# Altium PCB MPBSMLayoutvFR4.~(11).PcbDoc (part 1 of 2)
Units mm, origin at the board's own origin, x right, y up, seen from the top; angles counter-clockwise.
Board outline 131.7 x 110.39 mm, 4 copper layers (Top Layer, Power, GroundPlane, Bottom Layer), stack 2.286 mm thick; 156 components, 77 nets, 429 pads, 117 vias.
Unrouted connection lines stored in the file: 25.
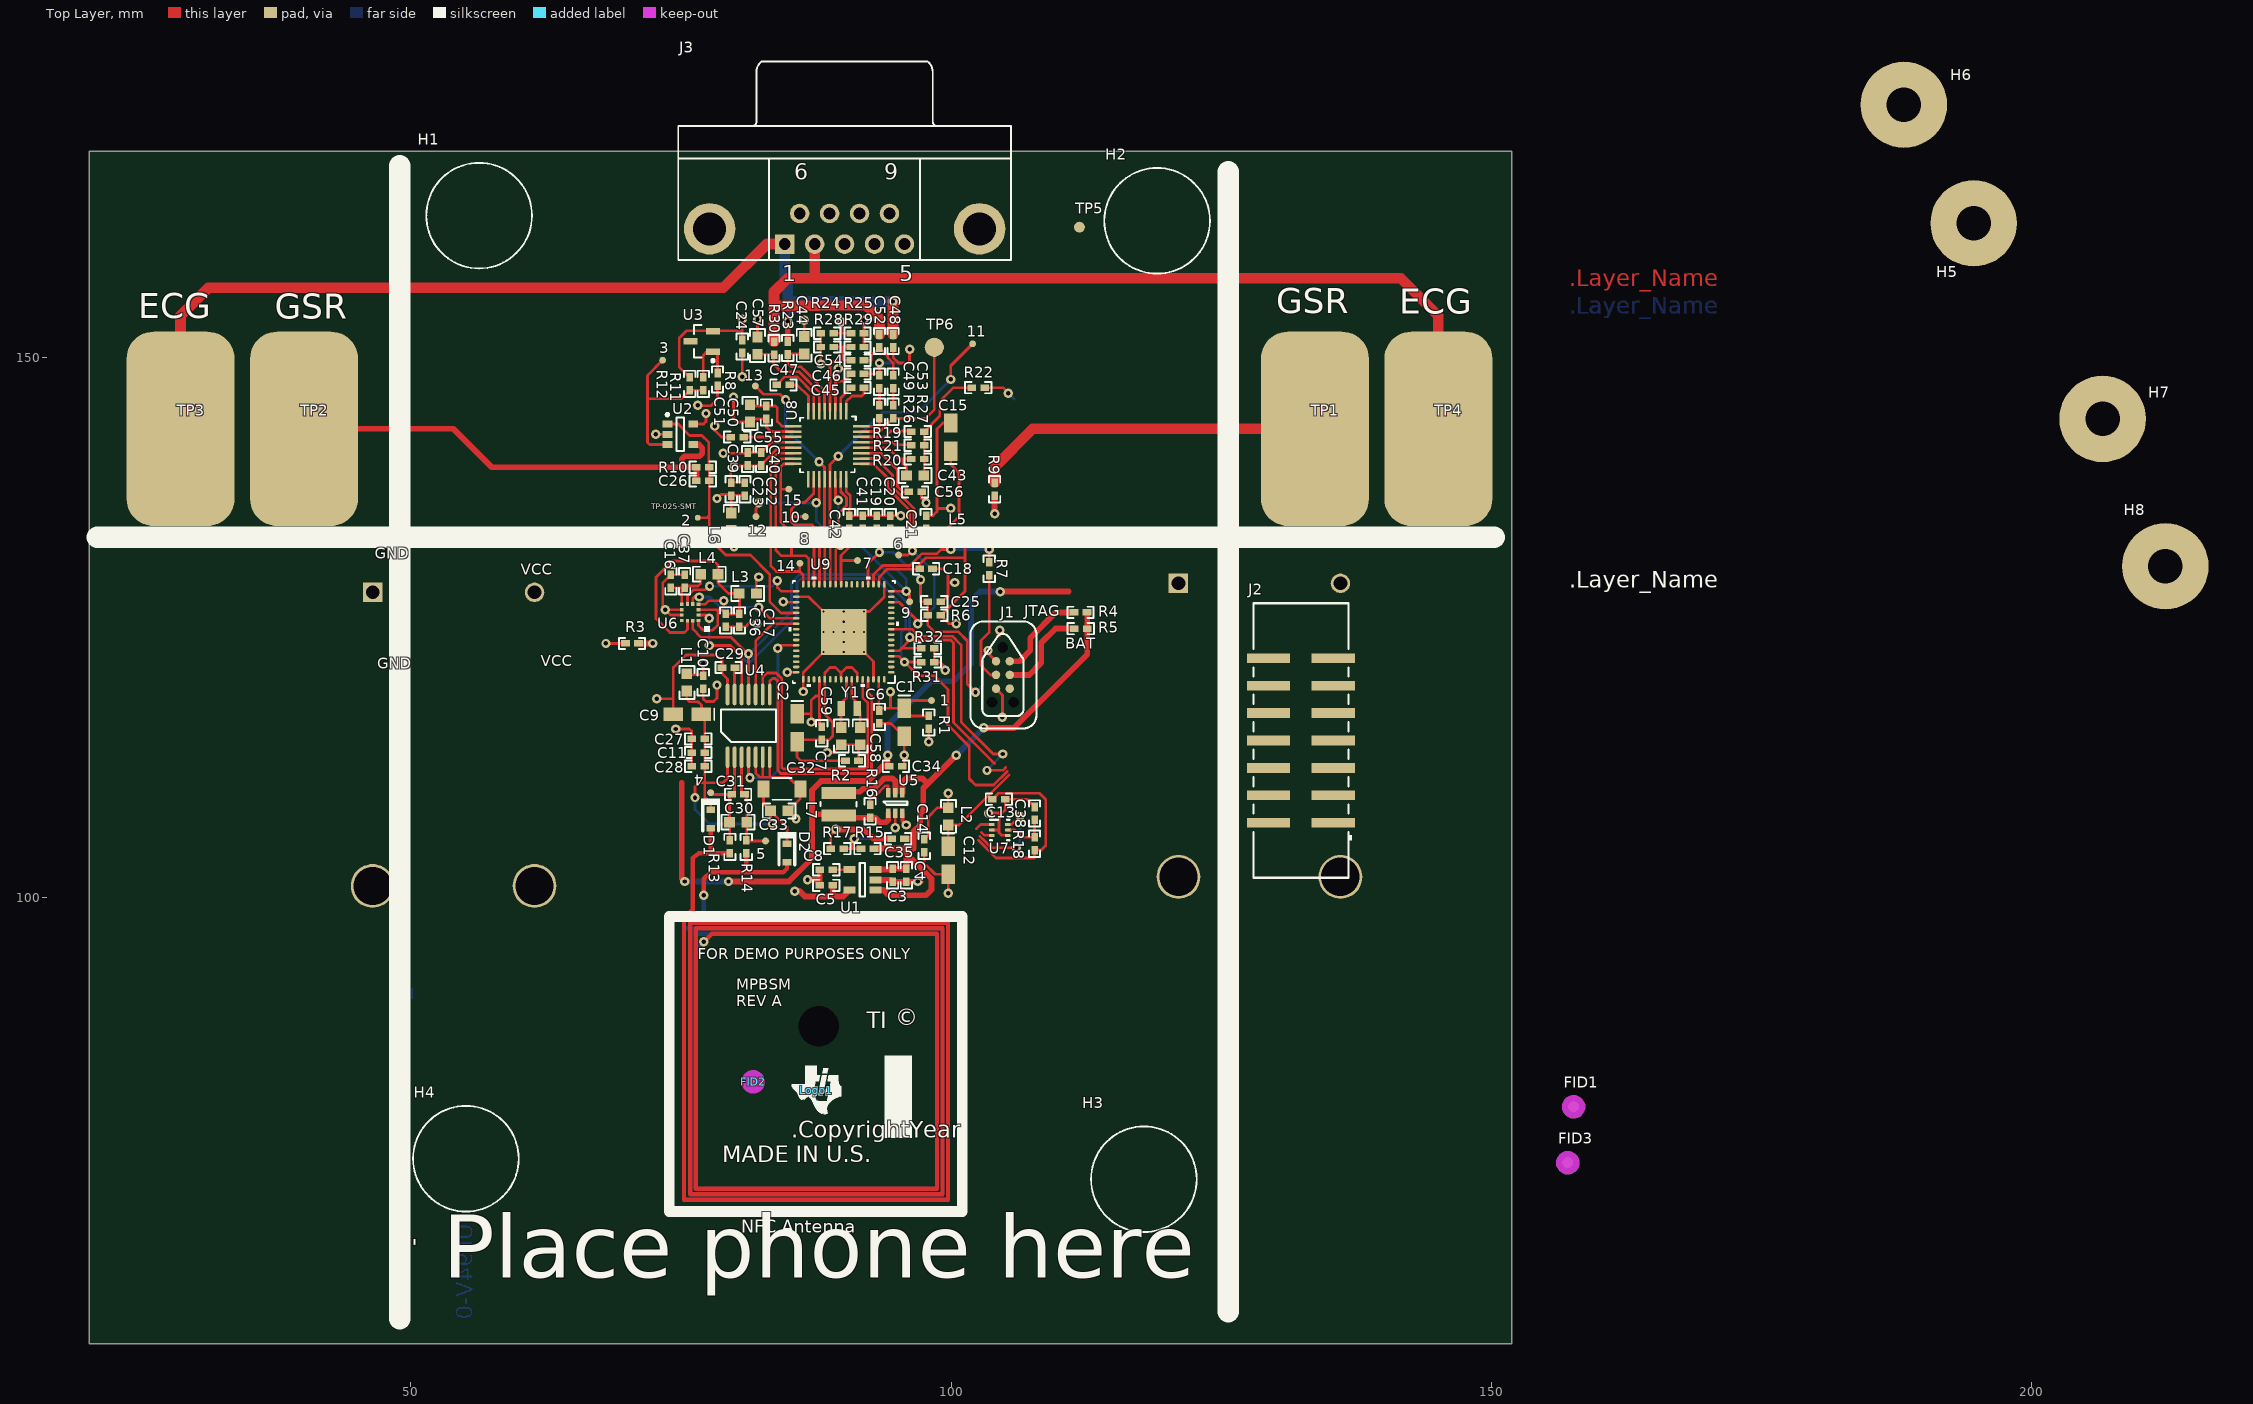
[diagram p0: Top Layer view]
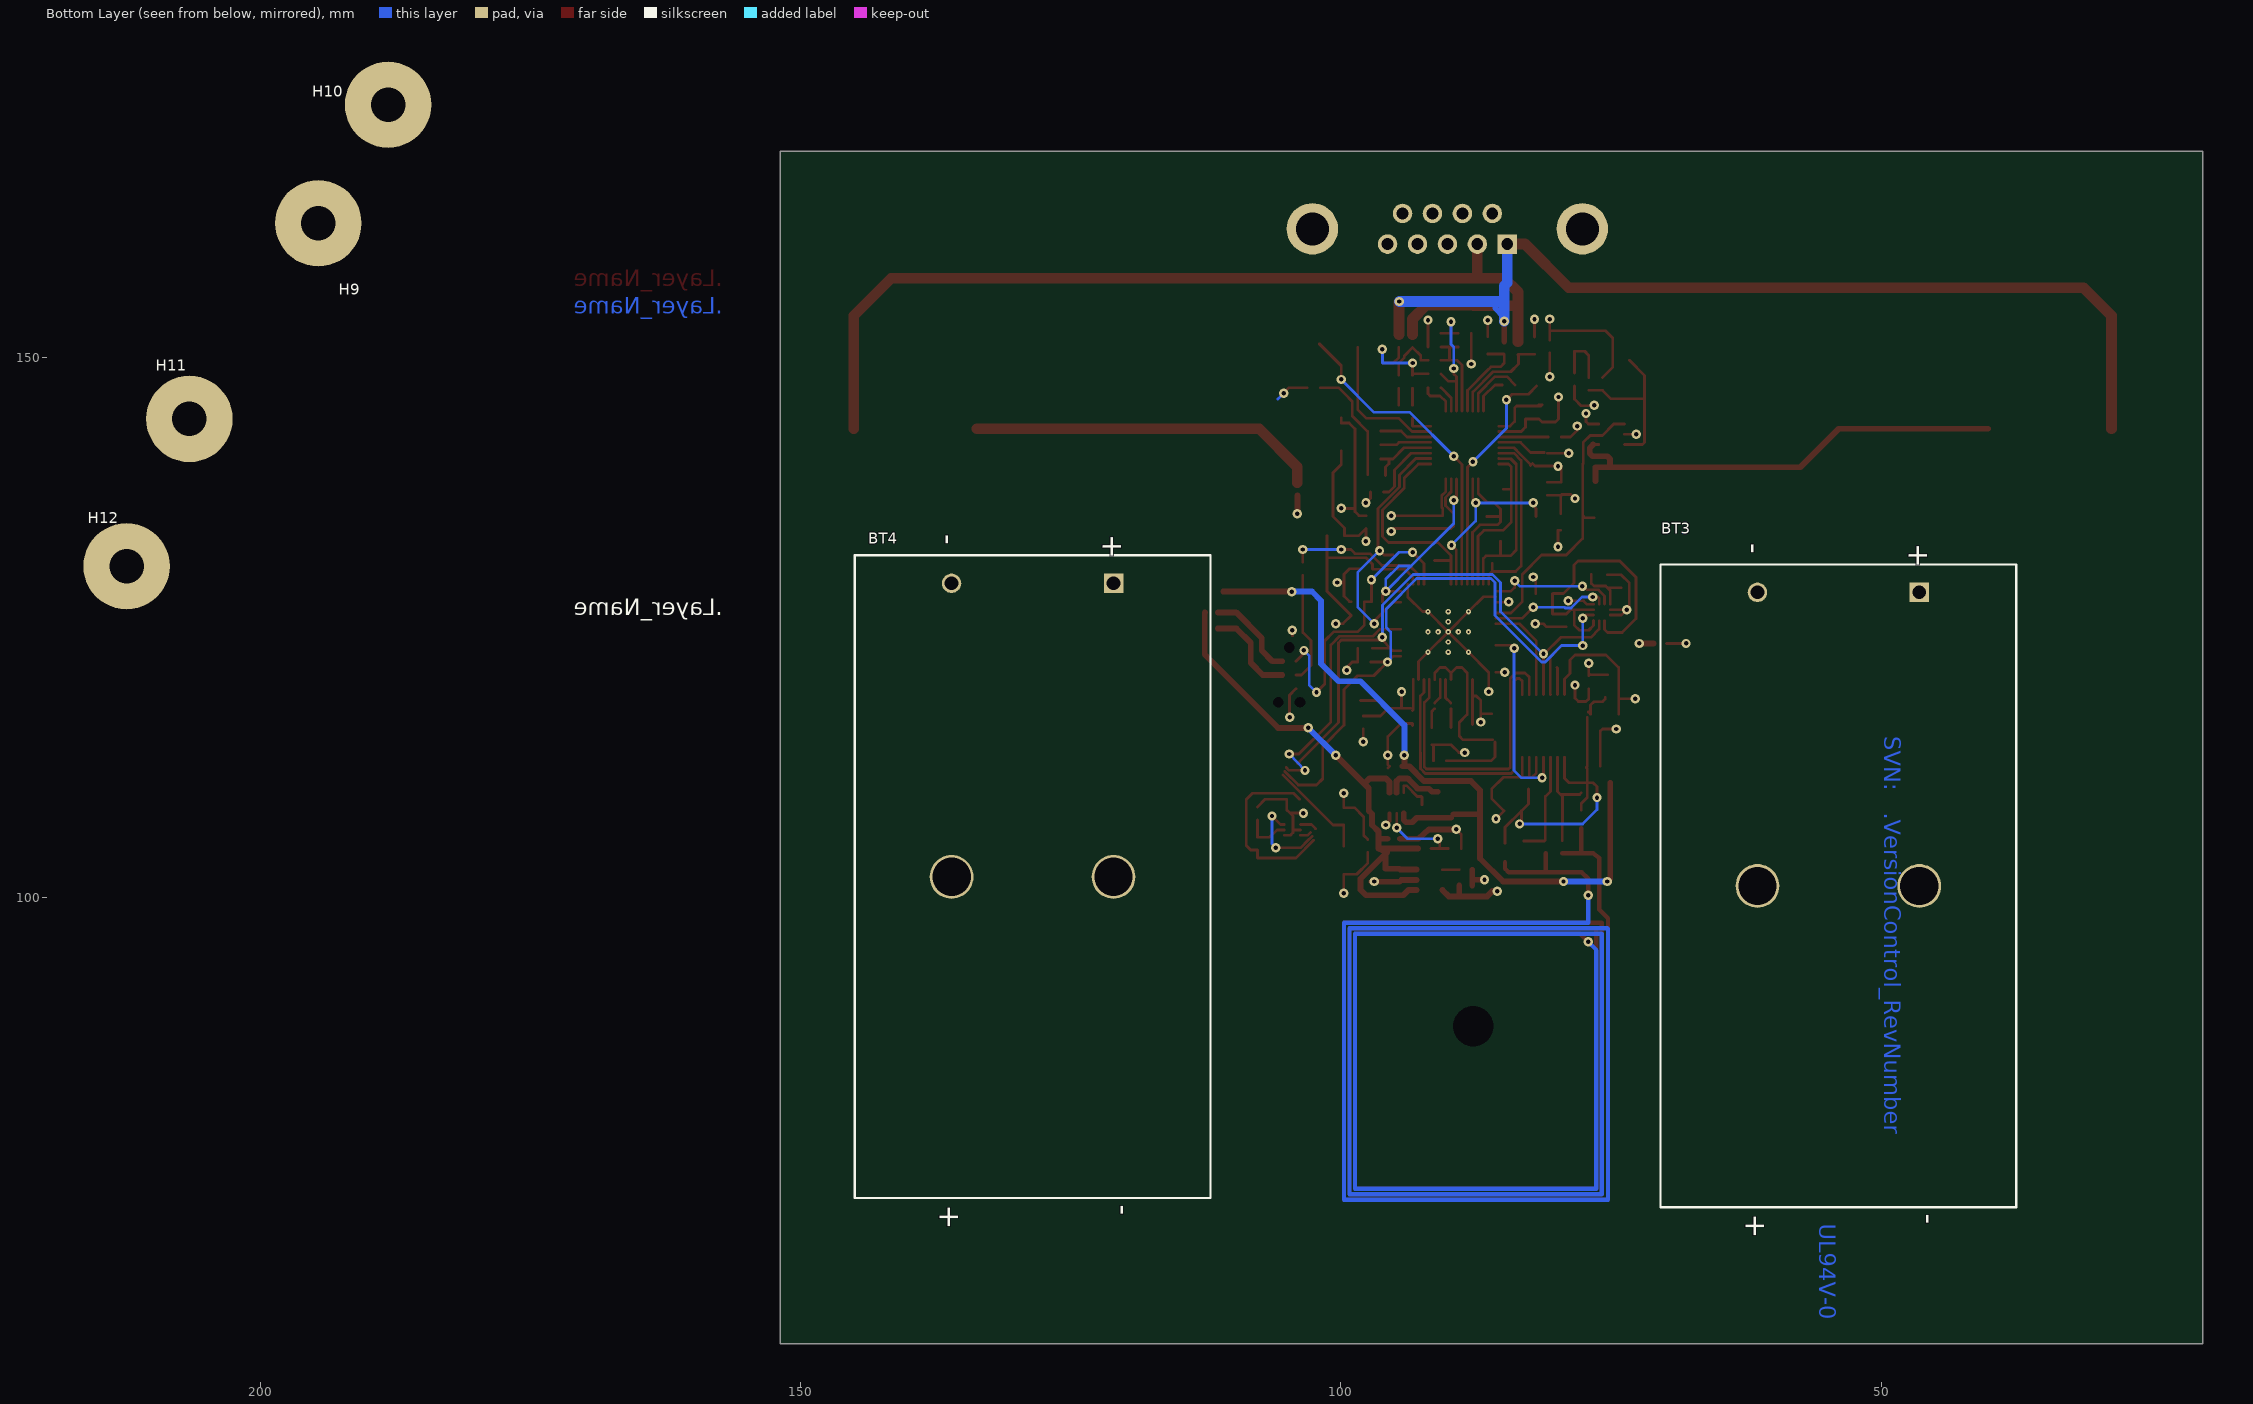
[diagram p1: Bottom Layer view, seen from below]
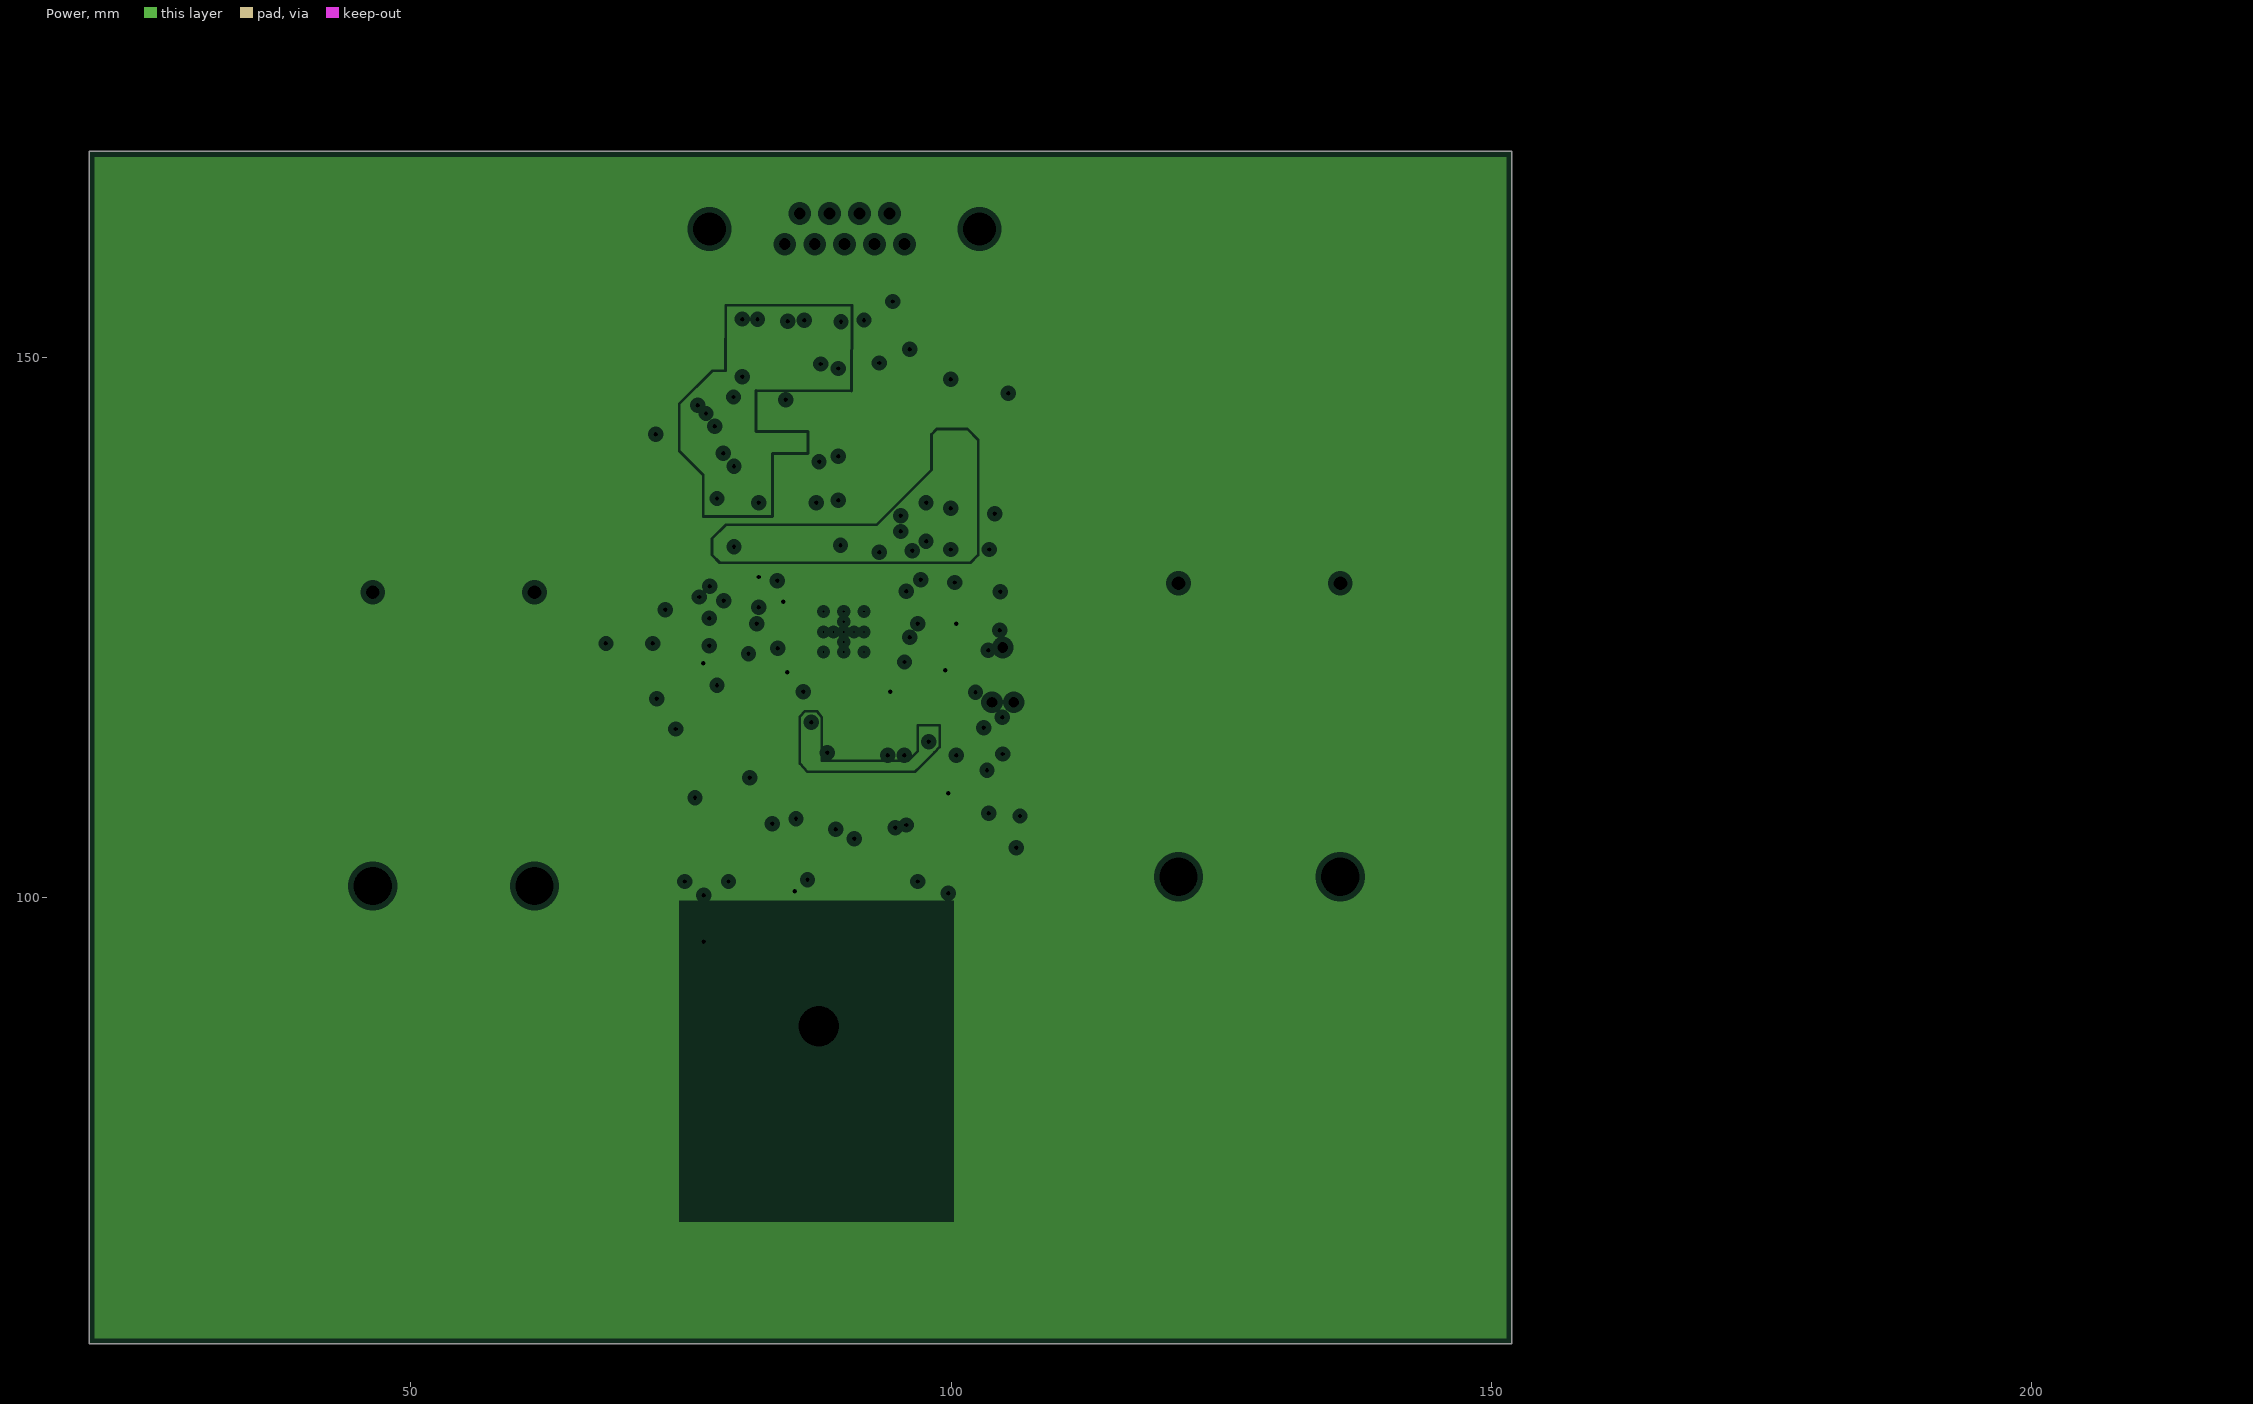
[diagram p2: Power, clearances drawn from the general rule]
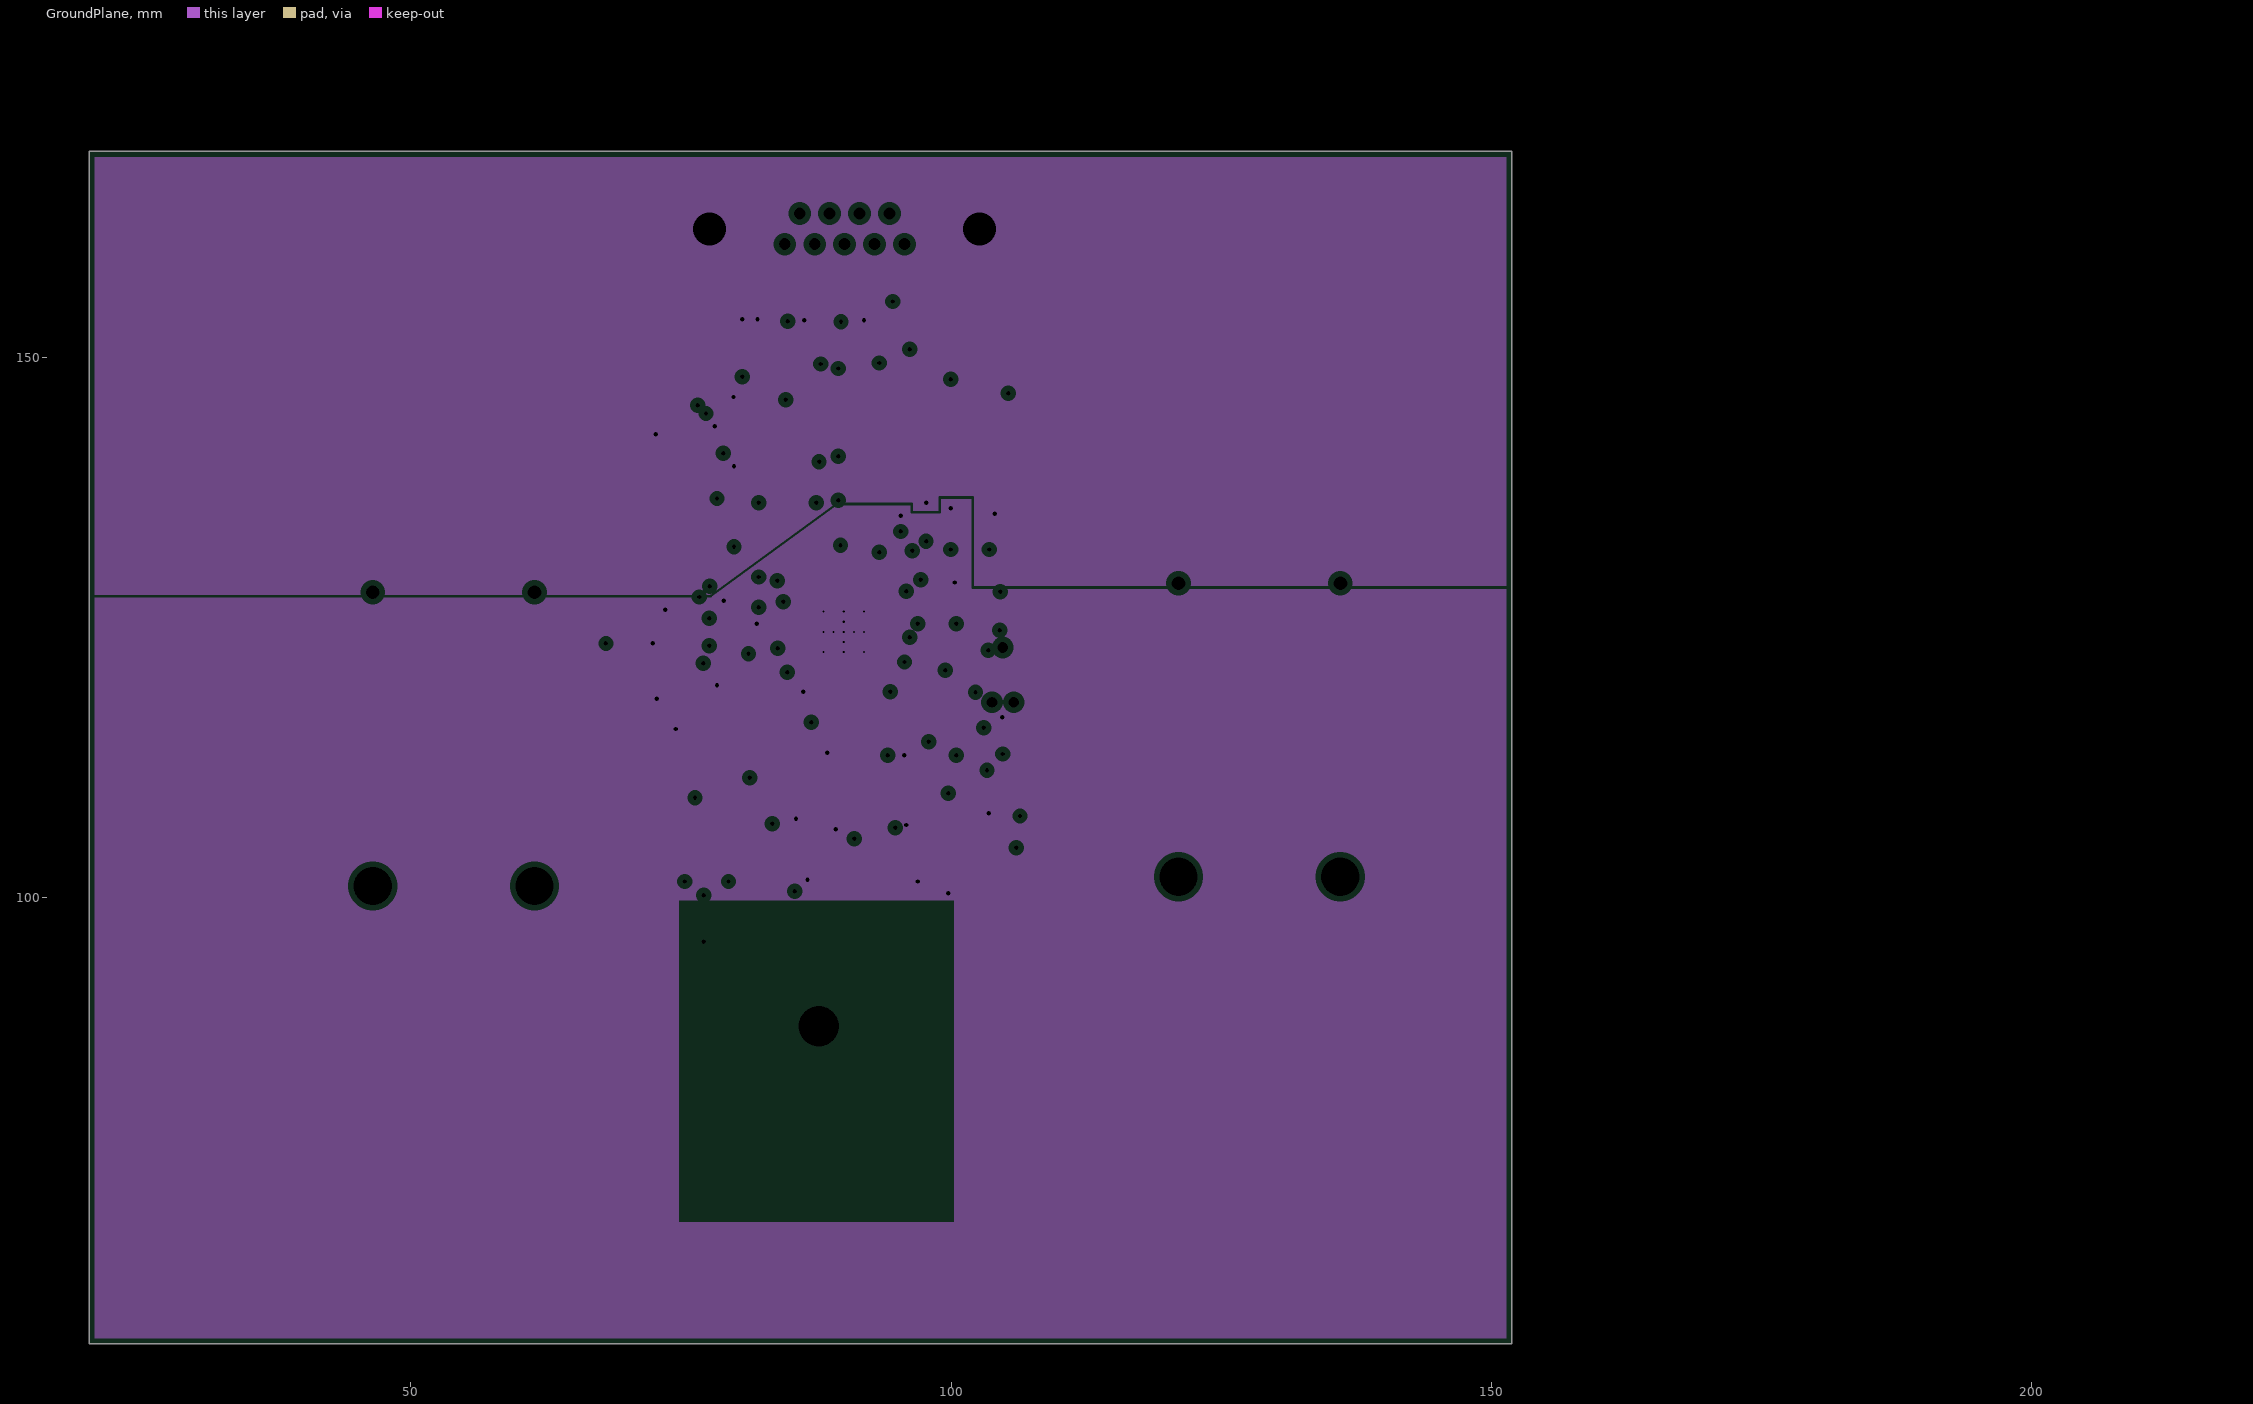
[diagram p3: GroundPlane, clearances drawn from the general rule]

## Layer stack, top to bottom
Top Solder: solder mask 0.0102, Solder Resist, Dk 3.5
Top Layer: signal copper 0.0356
Dielectric1: core 1.5037, FR-4, Dk 4.8
Power: plane copper 0.0356, net DVCC
Dielectric2: prepreg 0.32, FR-4, Dk 4.8
GroundPlane: plane copper 0.0356, net GND
Dielectric3: core 0.32, FR-4, Dk 4.8
Bottom Layer: signal copper 0.0356
Bottom Solder: solder mask 0.0102, Solder Resist, Dk 3.5

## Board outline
20.218,169.037 20.218,58.649 150.825,58.649 151.917,58.649 151.917,158.471 151.917,169.037 20.218,169.037

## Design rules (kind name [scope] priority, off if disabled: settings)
AcuteAngle [All] p1: minimum=4.50000000000000E+0001 checktracksonly=FALSE
AssemblyTestPointUsage [All] p1: valid=2
Clearance Clearance_BoardEdge_MountingHoles [OnCopper and InComponentClass('Mounting Holes') vs IsKeepOut] p1: gap=1.016
Clearance Clearance_BoardEdge_Poly [OnCopper and InPoly vs IsKeepOut] p2: gap=0.635
Clearance Clearance_BoardEdge [OnCopper and Not InComponentClass('Logo') and not InComponentClass('FiducialMark') and not InRegion(1000,500,4000,800) and Not IsKeepout vs IsKeepOut] p3: gap=1.905
Clearance Clearance_Poly [InPolygon] p4: gap=0.635
Clearance [All] p5: gap=0.1
ComponentClearance ComponentClearance_Shunt [InComponentClass('Header') vs InComponentClass('Shunt')] p1: gap=0 collisioncheckmode=3 verticalgap=0 showdistances=FALSE
ComponentClearance ComponentClearance_MountingHoles_FiducialMarks [InComponentClass('Mounting Holes') vs InComponentClass('FiducialMark')] p2: gap=1.27 collisioncheckmode=3 verticalgap=0.254 showdistances=FALSE
ComponentClearance ComponentClearance_Logo [InComponentClass('Logo')] p3: gap=1.27 collisioncheckmode=3 verticalgap=0.254 showdistances=FALSE
ComponentClearance ComponentClearance_ScrewToNut [(HasFootprint('NY PMS 440 0025 PH')) vs (HasFootprint('Keystone_1902C'))] p4: gap=0.127 collisioncheckmode=3 verticalgap=0.254 showdistances=FALSE
ComponentClearance ComponentClearance_MountingHoles [InComponentClass('Mounting Holes')] p5: gap=6.35 collisioncheckmode=3 verticalgap=2540 showdistances=FALSE
ComponentClearance ComponentClearance_SmallPassives [HasFootprint('0201*') or HasFootprint('0402*') or HasFootprint('0508') or HasFootprint('0603*') or HasFootprint('0612') or HasFootprint('0805*') or HasFootprint('0815*') or HasFootprint('0830*') or HasFootprint('1206*') or HasFootprint('1210*') or HasFootprint('1808*') or HasFootprint('1812*') or HasFootprint('1825*') or HasFootprint('2010*') or HasFootprint('2220*') or HasFootprint('2225*') or HasFootprint('2512*') or HasFootprint('2728*') or HasFootprint('3518*') vs HasFootprint('0201*') or HasFootprint('0402*') or HasFootprint('0508') or HasFootprint('0603*') or HasFootprint('0612') or HasFootprint('0805*') or HasFootprint('0815*') or HasFootprint('0830*') or HasFootprint('1206*') or HasFootprint('1210*') or HasFootprint('1808*') or HasFootprint('1812*') or HasFootprint('1825*') or HasFootprint('2010*') or HasFootprint('2220*') or HasFootprint('2225*') or HasFootprint('2512*') or HasFootprint('2728*') or HasFootprint('3518*')] p6: gap=0.508 collisioncheckmode=3 verticalgap=0.254 showdistances=FALSE
ComponentClearance ComponentClearance_THtoSMT [IsThruComponent vs IsSMTComponent] p7: gap=2.54 collisioncheckmode=3 verticalgap=0.762 showdistances=FALSE
ComponentClearance ComponentClearance_THtoTH [IsThruComponent vs IsThruComponent] p8: gap=3 collisioncheckmode=3 verticalgap=0.762 showdistances=FALSE
ComponentClearance [All] p9: gap=1.016 collisioncheckmode=3 verticalgap=0.254 showdistances=FALSE
DiffPairsRouting [All] p1: maxlimit=2.54 minlimit=0.254 mostfreqgap=0.254 toplayer_minwidth=0.381 toplayer_maxwidth=0.381 toplayer_prefwidth=0.381 bottomlayer_minwidth=0.381 bottomlayer_maxwidth=0.381 bottomlayer_prefwidth=0.381 maxuncoupledlength=25.4
FabricationTestPointUsage TestPointUsage [All] p1: valid=2 allowmultiple=FALSE
FabricationTestpoint Testpoint [All] p1: side=3 testpointundercomponent=TRUE minsize=1.016 maxsize=2.54 preferedsize=1.524 minholesize=0 maxholesize=1.016 preferedholesize=0.813 testpointgrid=0.025 allowsidetop=TRUE allowsidebottom=TRUE usegrid=TRUE gridtolerance=0
FanoutControl Fanout_LCC [IsLCC] p1: bgadir=Out bgaviamode=Centered fanoutstyle=Auto fanoutdirection=Alternating viagrid=0.025 // Fanout_LCC (Default Rule)
FanoutControl Fanout_BGA [IsBGA] p2: bgadir=Out bgaviamode=Centered fanoutstyle=Auto fanoutdirection=Alternating viagrid=0.025 // Fanout_BGA (Default Rule)
FanoutControl Fanout_Default [All] p4: bgadir=Out bgaviamode=Centered fanoutstyle=Auto fanoutdirection=Alternating viagrid=0.025 // Fanout_Default (Default Rule)
FanoutControl Fanout_Small [(CompPinCount < 5)] p5: bgadir=Out bgaviamode=Centered fanoutstyle=Auto fanoutdirection=OutThenIn viagrid=0.025 // Fanout_Small (Default Rule)
Height [All] p1: minheight=0 maxheight=55.4 prefheight=12.7
HoleSize [All] p1: absolutevalues=TRUE maxlimit=6.375 minlimit=0.1 maxpercent=80.000 minpercent=20.000
MinimumAnnularRing MinimumAnnularRing_ThermalPadVias [IsVia and InAnyComponent] p1: minimumring=0.15
MinimumAnnularRing [All] p2: minimumring=0.229
MinimumSolderMaskSliver MinimumSolderMaskSliver_Logo [InComponentClass('Logo') vs InComponentClass('Logo')] p1: minsoldermaskwidth=0.018
MinimumSolderMaskSliver [All] p2: minsoldermaskwidth=0.08
PlaneClearance [All] p1: clearance=0.508
PlaneConnect [All] p1: planeconnectstyle=Relief reliefexpansion=0.254 reliefentries=4 reliefconductorwidth=0.254 reliefairgap=0.254
PolygonConnect [All] p1: connectstyle=Relief reliefconductorwidth=0.254 reliefentries=4 polygonreliefangle="90 Angle" airgapwidth=0.254
RoutingVias ThermalPadVias [IsVia and InAnyComponent] p1: holewidth=0.2 width=0.5 viastyle="Through Hole" minholewidth=0.2 minwidth=0.5 maxholewidth=0.33 maxwidth=0.6
RoutingVias [All] p2: holewidth=0.406 width=0.864 viastyle="Through Hole" minholewidth=0.2 minwidth=0.66 maxholewidth=1.016 maxwidth=1.651
SMDToCorner [All] p1: distance=30000
SilkToSilkClearance SilkToSilkClearance_Pb-FreeLogo [(HasFootprint('Pb-Free_Overlay_Medium') OR HasFootprint('Pb-Free_Overlay_Small')) vs (HasFootprint('Pb-Free_Overlay_Medium') OR HasFootprint('Pb-Free_Overlay_Small'))] p1: silktosilkclearance=0
SilkToSilkClearance [All] p2: silktosilkclearance=0
SilkToSolderMaskClearance SilkscreenOverComponentPads [IsPad] p1: minsilkscreentomaskgap=0.127 clearancetoexposedcopper=TRUE
SolderMaskExpansion [All] p1: expansion=0.05
Width [All] p1: maxlimit=2.54 minlimit=0.152 preferedwidth=0.254 checkconnectedcopper=TRUE
14 further rules are at their usual default settings.

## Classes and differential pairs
component class Logo: Logo1
component class Designator: FID1 FID2 FID3 H1 H2 H3 H4 H5 H6 H7 H8 H9 H10 H11 H12 Logo1 ZZ1 ZZ2 ZZ3 ZZ4
component class FiducialMark: FID1 FID2 FID3
component class AssemblyNote: ZZ1 ZZ2 ZZ3 ZZ4
component class Battery: BT3 BT4 U?
component class BMA280: C36 C37 U6
component class "Boost Converter": C34 C35 L7 R15 R16 R17 U5
component class ECG: 6 7 8 9 10 11 12 13 14 15 C39 C40 C41 C42 C43 C44 C45 C46 C47 C48 C49 C50 C51 C52 C53 C54 C55 C56 C57 R19 R20 R21 R22 R23 R24 R25 R26 R27 R28 R29 R30 TP6 U8
component class GSR: 2 3 C26 R8 R9 R10 R11 R12 U2 U3
component class "JTAG SPY-BY-WIRE": C25 J1 J2 R4 R5 R6 R7
component class MSP430FR5XXX: C58 C59 R31 R32 U9 Y1
component class "Power Filtering": 1 C1 C2 C3 C4 C5 C6 C7 C8 C9 C10 C11 C12 C13 C14 C15 C16 C17 C18 C19 C20 C21 C22 C23 C24 L1 L2 L3 L4 L5 L6 R1 R2 R3 U1
component class Temperature: C38 R18 U7
component class Transponder: 4 5 C27 C28 C29 C30 C31 C32 C33 D1 D2 R13 R14 U4
component class "Analog Connector": J3
component class "Mounting Holes": H5 H6 H7 H8

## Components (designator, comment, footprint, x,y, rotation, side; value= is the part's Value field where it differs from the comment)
1 "TP-025-SMT" TP_25MIL-SMT#1 98.196,118.212 r90 top
2 "TP-025-SMT" TP_25MIL-SMT#2 76.556,135.128 r0 top
3 "TP-025-SMT" TP_25MIL-SMT#1 73.304,149.708 r0 top
4 "TP-025-SMT" TP_25MIL-SMT#1 77.745,109.676 r0 top
5 "TP-025-SMT" TP_25MIL-SMT#1 82.829,105.207 r270 top
6 "TP-025-SMT" TP_25MIL-SMT#1 95.148,131.674 r0 top
7 "TP-025-SMT" TP_25MIL-SMT#1 91.338,131.166 r0 top
8 "TP-025-SMT" TP_25MIL-SMT#1 85.242,133.198 r0 top
9 "TP-025-SMT" TP_25MIL-SMT#1 96.164,127.356 r0 top
10 "TP-025-SMT" TP_25MIL-SMT#1 86.512,135.23 r0 top
11 "TP-025-SMT" TP_25MIL-SMT#1 102.006,151.232 r0 top
12 "TP-025-SMT" TP_25MIL-SMT#1 81.94,135.23 r0 top
13 "TP-025-SMT" TP_25MIL-SMT#1 81.89,147.32 r0 top
14 "TP-025-SMT" TP_25MIL-SMT#1 86.004,130.912 r90 top
15 "TP-025-SMT" TP_25MIL-SMT#1 84.988,137.77 r0 top
BT3 "2462" Keystone_2462 53.95,114.63 r270 bottom
BT4 "2462" Keystone_2462 128.549,115.468 r270 bottom
C1 "293D106X9010A2TE3" 3216-18 95.656,116.18 r270 top
C2 "293D106X9010A2TE3" 3216-18 85.75,115.672 r270 top
C3 "C1005X5R1A104K" 0402 94.594,102.028 r270 top
C4 "C1005X5R0J105M" 0402 95.864,102.028 r270 top
C5 "C1005X5R1C225K050BC" 0402 88.448,101.092 r180 top
C6 "C1005X5R1A104K" 0402 93.37,116.688 r270 top
C7 "C1005X5R1A104K" 0402 88.036,115.164 r270 top
C8 "C1005X7R1E103K" 0402 88.443,102.54 r180 top
C9 "293D105X9016A2TE3" 3216-18 75.59,116.942 r180 top
C10 "C1005X5R1A104K" 0402 77.064,119.888 r270 top
C11 "C1005X5R1A104K" 0402 76.606,113.386 r180 top
C12 "293D106X9010A2TE3" 3216-18 99.753,103.422 r270 top
C13 "C1005X5R1A104K" 0402 104.429,109.068 r0 top
C14 "C1005X5R1A104K" 0402 97.513,104.75 r270 top
C15 "293D105X9016A2TE3" 3216-18 99.974,142.596 r90 top
C16 "CL05A106MQ5NUNC" 0402 74.066,129.247 r90 top
C17 "CL05A106MQ5NUNC" 0402 80.416,125.624 r270 top
C18 "C1005X5R1A104K" 0402 97.688,130.404 r0 top
C19 "C1005X5R1A104K" 0402 93.116,134.722 r90 top
C20 "C1005X5R1C225K050BC" 0402 94.386,134.722 r90 top
C21 "CL05A106MQ5NUNC" 0402 97.688,134.722 r90 top
C22 "CL05A106MQ5NUNC" 0402 80.924,137.77 r90 top
C23 "C1005X5R1A104K" 0402 79.654,137.77 r90 top
C24 "C1005X5R1A104K" 0402 80.67,150.978 r90 top
C25 "C1005X8R1H222K" 0402 98.45,127.356 r0 top
C26 "C1005X7R1E103K" 0402 77.022,138.532 r180 top
C27 "C1005X5R0J105M" 0402 76.606,114.656 r180 top
C28 "C1005X5R1A104K" 0402 76.606,112.116 r180 top
C29 "GRM155R60J474KE19D" 0402 79.4,121.26 r0 top
C30 "C1608C0G1H330J" 0603 80.285,106.941 r0 top
C31 "GRM1555C1H390JA01D" 0402 80.285,109.515 r0 top
C32 "C3216X5R1A107M160AC" 1206_190 84.349,110.023 r0 top
C33 "Used in BOM report" 0603 84.095,107.991 r0 top
C34 "CL05A106MQ5NUNC" 0402 94.894,112.116 r0 top
C35 "CL05A106MQ5NUNC" 0402 95.098,105.41 r180 top
C36 "C1005X5R1A104K" 0402 79.146,125.624 r270 top
C37 "C1005X5R1A104K" 0402 75.336,129.247 r90 top
C38 "C1005X7R1E103K" 0402 107.731,107.752 r90 top
C39 "C1005X5R1C105K050BC" 0402 81.178,140.564 r270 top
C40 "C1005X5R1A104K" 0402 82.448,140.564 r270 top
C41 "C1005X5R1C105K050BC" 0402 91.846,134.722 r90 top
C42 "C1005X5R1A104K" 0402 90.576,134.722 r90 top
C43 "C0603C152K5RACTU" 0603 96.672,139.04 r180 top
C44 "GRM1885C1H302JA01D" 0603 86.411,151.091 r90 top
C45 "GRM155R61A472KA01D" 0402 91.338,147.168 r0 top
C46 "C1005X8R1H222K" 0402 91.338,148.438 r0 top
C47 "GRM155R61A472KA01D" 0402 84.48,147.422 r180 top
C48 "C1005X5R1A104K" 0402 94.64,151.486 r270 top
C49 "C1005X8R1H222K" 0402 93.37,147.722 r90 top
C50 "C1005X5R1A104K" 0402 82.906,144.872 r270 top
C51 "C1608X5R0J106M" 0603 81.382,144.78 r270 top
C52 "C1005X5R1A104K" 0402 93.37,151.486 r270 top
C53 "C1005X8R1H222K" 0402 94.64,147.722 r90 top
C54 "C1005X8R1H222K" 0402 91.338,149.708 r0 top
C55 "C1005X5R1C105K050BC" 0402 80.208,142.596 r180 top
C56 "C1005X5R1C105K050BC" 0402 96.672,137.516 r0 top
C57 "GRM1885C1H302JA01D" 0603 82.089,151.063 r90 top
C58 "06035A100JAT2A" 0603 91.592,114.91 r270 top
C59 "06035A100JAT2A" 0603 89.84,114.91 r270 top
D1 "CDBU0130L" SOD-523F 77.745,107.229 r270 top
D2 "CDBU0130L" SOD-523F 84.811,104.089 r270 top
FID1 "Fiducial" Fiducial10-20 157.632,80.594 r0 top
FID2 "Fiducial" Fiducial10-20 81.686,82.906 r0 top
FID3 "Fiducial" Fiducial10-20 157.099,75.413 r0 top
H1 "SJ61A2" Bumpon_SJ61A2 56.312,163.093 r0 top
H2 "SJ61A2" Bumpon_SJ61A2 119.075,162.611 r0 top
H3 "SJ61A2" Bumpon_SJ61A2 117.856,73.889 r0 top
H4 "SJ61A2" Bumpon_SJ61A2 55.093,75.794 r0 top
H5 "NY PMS 440 0025 PH" "NY PMS 440 0025 PH" 194.666,162.382 r90 top
H6 "NY PMS 440 0025 PH" "NY PMS 440 0025 PH" 188.214,173.355 r90 top
H7 "NY PMS 440 0025 PH" "NY PMS 440 0025 PH" 206.604,144.272 r90 top
H8 "NY PMS 440 0025 PH" "NY PMS 440 0025 PH" 212.421,130.638 r90 top
H9 "1902C" Keystone_1902C 194.665,162.376 r90 bottom
H10 "1902C" Keystone_1902C 188.239,173.33 r90 bottom
H11 "1902C" Keystone_1902C 206.604,144.272 r90 bottom
H12 "1902C" Keystone_1902C 212.42,130.632 r180 bottom
J1 "TC2030-MCP-NL" TC2030-MCP-NL 104.8,120.574 r180 top
J2 "61201420621" Wurth_61201420621 132.385,114.503 r180 top
J3 "182-009-213R171" NORCOMP_182-009-213R171 90.145,171.374 r0 top
L1 "BLM18HG601SN1D" 0603 75.54,119.888 r270 top
L2 "BLM18HG601SN1D" 0603 99.753,107.486 r270 top
L3 "BLM18HG601SN1D" 0603 81.178,128.118 r180 top
L4 "BLM18HG601SN1D" 0603 77.622,129.896 r0 top
L5 "BLM18HG601SN1D" 0603 100.482,133.452 r180 top
L6 "BLM18HG601SN1D" 0603 79.654,134.772 r90 top
L7 "EPL3015-472MLB" EPL3015 89.586,108.61 r90 top
Logo1 "Texas Instruments" TI_Symbol_Overlay_Small 87.528,82.144 r0 top
R1 "ERJ-2GE0R00X" 0402 97.942,116.18 r270 top
R2 "ERJ-2GE0R00X" 0402 90.83,112.624 r180 top
R3 "ERJ-2GE0R00X" 0402 70.469,123.489 r180 top
R4 "ERJ-2GE0R00X" 0402 111.989,126.365 r0 top
R5 "ERJ-2GE0R00X" 0402 112.008,124.861 r0 top
R6 "CRCW040247K0JNED" 0402 98.45,126.086 r0 top
R7 "ERJ-2GE0R00X" 0402 103.53,130.404 r90 top
R8 "CRCW040221K5FKED" 0402 78.384,147.93 r270 top
R9 "CRCW040210K0FKED" 0402 104.038,137.77 r90 top
R10 "ERJ-2RKF1004X" 0402 77.022,139.802 r0 top
R11 "CRCW040211K8FKED" 0402 77.069,147.517 r90 top
R12 "CRCW04028K06FKED" 0402 75.799,147.517 r270 top
R13 "ERJ-2GE0R00X" 0402 79.523,104.655 r270 top
R14 "ERJ-2GE0R00X" 0402 81.047,104.655 r270 top
R15 "ERJ-2RKF1004X" 0402 92.262,104.496 r0 top
R16 "ERJ-2GE0R00X" 0402 92.507,107.95 r90 top
R17 "ERJ-2RKF2003X" 0402 89.468,104.496 r0 top
R18 "CRCW04024K99FKED" 0402 107.731,104.958 r270 top
R19 "ERJ-2GE0R00X" 0402 96.926,143.104 r0 top
R20 "ERJ-2RKF1004X" 0402 96.926,140.564 r0 top
R21 "ERJ-2RKF1003X" 0402 96.926,141.834 r0 top
R22 "ERJ-2RKF1003X" 0402 102.514,147.168 r0 top
R23 "CRCW040251K1FKED" 0402 84.887,150.837 r270 top
R24 "CRCW040210M0FKED" 0402 88.544,152.202 r180 top
R25 "CRCW040210M0FKED" 0402 91.338,152.202 r180 top
R26 "CRCW040240K2FKED" 0402 93.37,144.928 r270 top
R27 "CRCW040240K2FKED" 0402 94.64,144.928 r270 top
R28 "CRCW040210M0FKED" 0402 88.544,150.932 r180 top
R29 "CRCW040210M0FKED" 0402 91.338,150.932 r180 top
R30 "CRCW040251K1FKED" 0402 83.613,150.809 r270 top
R31 "CRCW04023K30JNED" 0402 97.85,121.768 r180 top
R32 "CRCW04023K30JNED" 0402 97.85,123.038 r180 top
TP1 "TESTPOINT" TP_SM_1MM#1 133.68,143.358 r0 top
TP2 "TESTPOINT" TP_SM_1MM#2 40.107,143.358 r90 top
TP3 "TESTPOINT" TP_SM_1MM#2 28.677,143.358 r90 top
TP4 "TESTPOINT" TP_SM_1MM#2 145.11,143.358 r90 top
TP5 "TESTPOINT" TP_SM_1MM#3 111.887,162.027 r90 top
TP6 "Pogo Pad" PogoPad 98.45,150.901 r0 top locked
U1 "TPS73030DBVR" DBV0005A_N 91.796,101.6 r180 top
U2 "LMP2231AMFE" MF05A_L 74.944,142.85 r0 top
U3 "LM4041AIM3-1.2" MF03A_N 76.911,151.46 r180 top
U4 "RF430CL331HCPW" PW0014A_M 81.261,115.864 r90 top
U5 "TPS61220DCK" DCK0006A_N 94.844,108.712 r90 top
U6 "BMA280" LGA-12P 75.844,126.361 r90 top
U7 "TMP112AIDRL" DRL0006A 104.504,106.221 r0 top
U8 "ADS1292RIPBS" PBS0032A_N 88.544,141.853 r270 top
U9 "MSP430FR5889IRGCR" RGC0064B 90.068,124.562 r180 top
Y1 "FC-12M 32.7680KA-A3" Epson_FC-12M 90.576,117.45 r0 top
ZZ1 "This Assembly Note is for PCB labels only" AssemblyNoteLabel 35.992,195.631 r0 top
ZZ2 "These assemblies are ESD sensitive, ESD precautions shall be observed." AssemblyNote 35.992,192.865 r0 top
ZZ3 "These assemblies must be clean and free from flux and all contaminants. Use of no clean flux is not acceptable." AssemblyNote 35.992,190.616 r0 top
ZZ4 "These assemblies must comply with workmanship standards IPC-A-610 Class 2, unless otherwise specified." AssemblyNote 35.992,188.366 r0 top

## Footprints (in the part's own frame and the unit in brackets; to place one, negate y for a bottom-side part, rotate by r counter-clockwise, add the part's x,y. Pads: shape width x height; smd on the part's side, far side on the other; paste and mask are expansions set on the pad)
0402 [mm] "0402 from SM-752 data"
  rect 0.8x0.6 smd: 1(-0.6,0) 2(0.6,0)
  silkscreen extent -1.22,-0.52 1.22,0.52, body extent -0.55,-0.3 0.55,0.3, height 0.6
0603 [mm] "0603 from SM-752 data"
  rect 1x0.95 smd: 1(-0.8,0) 2(0.8,0)
  silkscreen extent -1.52,-0.69 1.52,0.69, body extent -0.87,-0.47 0.87,0.47, height 0.85
1206_190 [mm] "1206_190"
  rect 1.1x1.6 smd: 1(-1.7,0) 2(1.7,0)
  silkscreen extent -0.9,-1 0.9,1, body extent -1.75,-0.95 1.75,0.95, height 1.9
3216-18 [mm] "Medium density IPC, based on Kemet T495 dimensions"
  rect 1.8x1.25 smd: 1(-1.3,0) 2(1.3,0)
  silkscreen extent -2.49,-0.54 -2.49,0.54, body extent -1.7,-0.9 1.7,0.9, height 1.8
AssemblyNote [mm] "Assembly Note"
AssemblyNoteLabel [mm] "Assembly Note for PCB Labels"
Bumpon_SJ61A2 [mil] "3M Hemispherical Bumpon transparent"
  round 1 on Mech3: 0(0,0)
  silkscreen extent -192,-192 192,192, body extent -191,-192 193,192, height 250
DBV0005A_N [mm] "SOT23, 5-Leads, Body 2.9x1.6mm, Pitch 0.95mm, Lead Span 2.8mm, IPC Medium Density"
  rect 1.1x0.65 smd: 1(-1.2,0.95) 2(-1.2,0) 3(-1.2,-0.95) 4(1.2,-0.95) 5(1.2,0.95)
  silkscreen extent -0.25,-1.55 0.25,1.55, body extent -1.42,-1.46 1.42,1.46, height 1.08
DCK0006A_N [mm] "SOT23, 6-Leads, Body 2x1.3mm, Pitch 0.65mm, Lead Span 2.1mm, IPC Medium Density"
  rect 0.85x0.4 smd: 1(-0.95,0.65) 2(-0.95,0) 3(-0.95,-0.65) 4(0.95,-0.65) 5(0.95,0) 6(0.95,0.65)
  silkscreen extent -0.15,-1.1 0.15,1.1, body extent -1.14,-1 1.14,1, height 0.94
DRL0006A [mm] "SOTFL, 6-Flat Leads, Body 1.2x1.6x0.6mm, Pitch 0.5mm, TI recommended"
  rect 0.5x0.3 smd: 1(-0.75,0.5) 2(-0.75,0) 3(-0.75,-0.5) 4(0.75,-0.5) 5(0.75,0) 6(0.75,0.5)
  silkscreen extent -0.9,-0.95 0.9,0.95, body extent -0.85,-0.85 0.85,0.85, height 0.62
EPL3015 [mm] "COILCRAFT"
  rect 1.12x3.2 smd: 1(-1.04,0) 2(1.04,0)
  silkscreen extent -0.22,-1.65 0.23,1.68, body extent -1.6,-1.6 1.6,1.6, height 1.55
Epson_FC-12M [mm] "Epson"
  rect 0.7x1.4 smd: 1(-0.75,0) 2(0.75,0)
  body extent -1.05,-0.63 1.05,0.63, height 0.6
Fiducial10-20 [mm]
  round 1 smd mask+0.5: 1(0,0)
  Top Layer keep-out circle w1.178: c0,0 r0.5
Keystone_1902C [mil] "Hex Standoff, 4-40 threaded, nylon"
  round 1 on Mech4: 0(0,0)
  body extent -145,-126 146,126, height 501
Keystone_2462 [mm] "2x AA Battery Holder, Through-hole mount"
  rect 1.8x1.8 hole 1.27: 1(-13.59,7.495)
  round 1.8 hole 1.27: 2(-13.59,-7.495)
  round 4.05 hole 3.55: 3(13.59,-7.495) 4(13.59,7.495)
  silkscreen extent -16.18,-16.46 43.33,16.46, body extent -16.31,-16.46 43.4,16.46, height 16
LGA-12P [mm]
  rect 0.3x0.35 smd mask+0.05: 1(-0.75,-0.775) 2(-0.25,-0.775) 3(0.25,-0.775) 4(0.75,-0.775) 7(0.75,0.775) 8(0.25,0.775) 9(-0.25,0.775) 10(-0.75,0.775)
  rect 0.35x0.3 smd mask+0.05: 5(0.775,-0.25) 6(0.775,0.25) 11(-0.775,0.25) 12(-0.775,-0.25)
  silkscreen extent -1.8,-1.8 -1.29,-1.3
MF03A_N [mm] "SOT23, 3-Leads, Body 2.9x1.3mm, Pitch 0.95mm, Lead Span 2.4mm, IPC Medium Density"
  rect 1.3x0.6 smd: 1(-1.05,0.95) 2(-1.05,-0.95) 3(1.05,0)
  silkscreen extent -1.18,-1.5 0.7,1.92, body extent -0.7,-1.5 0.7,1.5, height 1.12
MF05A_L [mm] "SOT23, 5-Leads, Body 2.9x1.6mm, Pitch 0.95mm, Lead Span 2.8mm, IPC High Density"
  rect 0.9x0.65 smd: 1(-1.2,0.95) 2(-1.2,0) 3(-1.2,-0.95) 4(1.2,-0.95) 5(1.2,0.95)
  silkscreen extent -1.32,-1.55 0.35,1.95, body extent -0.9,-1.55 0.9,1.55, height 1.19
NORCOMP_182-009-213R171 [mm] "Connector; D Subminiature 9 Position; Right Angle"
  rect 1.8x1.8 hole 1.092: 1(-5.54,-10.92)
  round 1.8 hole 1.092: 2(-2.77,-10.92) 3(0,-10.92) 4(2.77,-10.92) 5(5.54,-10.92) 6(-4.155,-8.08) 7(-1.385,-8.08) 8(1.385,-8.08) 9(4.155,-8.08)
  round 4.76 hole 3.05: 10(-12.495,-9.5) 11(12.495,-9.5)
  silkscreen extent -15.4,-12.4 15.4,6, body extent -15.41,-12.98 15.41,6.1, height 12.55
"NY PMS 440 0025 PH" [mm] "4-40 nylon screw and mounting hole"
  round 8 hole 3.2: 1(0,0)
  body extent -3.3,-3.3 3.3,3.3, height 2.69
PBS0032A_N [mil]
  rect 60x9 smd: 1(-124,68.9) 2(-124,49.21) 3(-124,29.53) 4(-124,9.84) 5(-124,-9.84) 6(-124,-29.53) 7(-124,-49.21) 8(-124,-68.9) 17(124,-68.9) 18(124,-49.21) 19(124,-29.53) 20(124,-9.84) 21(124,9.84) 22(124,29.53) 23(124,49.21) 24(124,68.9)
  rect 9x60 smd: 9(-68.9,-124) 10(-49.21,-124) 11(-29.53,-124) 12(-9.84,-124) 13(9.84,-124) 14(29.53,-124) 15(49.21,-124) 16(68.9,-124) 25(68.9,124) 26(49.21,124) 27(29.53,124) 28(9.84,124) 29(-9.84,124) 30(-29.53,124) 31(-49.21,124) 32(-68.9,124)
  silkscreen extent -104,-100 100,104, body extent -140,-140 140,140, height 48
PogoPad [mil] "No Solder Paste"
  round 70 smd paste-35: 1(0,0)
PW0014A_M [mm] "TSOP, 14-Leads, Body 5x4.4mm, Pitch 0.65mm, IPC Low Density"
  oval 2x0.35 smd: 1(-2.9,1.95) 2(-2.9,1.3) 3(-2.9,0.65) 4(-2.9,0) 5(-2.9,-0.65) 6(-2.9,-1.3) 7(-2.9,-1.95) 8(2.9,-1.95) 9(2.9,-1.3) 10(2.9,-0.65) 11(2.9,0) 12(2.9,0.65) 13(2.9,1.3) 14(2.9,1.95)
  silkscreen extent -1.5,-2.55 1.53,2.55, body extent -3.21,-2.5 3.21,2.5, height 0.98
RGC0064B [mm]
  oval 0.6x0.24 smd mask+0.07: 1(-4.4,3.75) 2(-4.4,3.25) 3(-4.4,2.75) 4(-4.4,2.25) 5(-4.4,1.75) 6(-4.4,1.25) 7(-4.4,0.75) 8(-4.4,0.25) 9(-4.4,-0.25) 10(-4.4,-0.75) 11(-4.4,-1.25) 12(-4.4,-1.75) 13(-4.4,-2.25) 14(-4.4,-2.75) 15(-4.4,-3.25) 16(-4.4,-3.75) 33(4.4,-3.75) 34(4.4,-3.25) 35(4.4,-2.75) 36(4.4,-2.25) 37(4.4,-1.75) 38(4.4,-1.25) 39(4.4,-0.75) 40(4.4,-0.25) 41(4.4,0.25) 42(4.4,0.75) 43(4.4,1.25) 44(4.4,1.75) 45(4.4,2.25) 46(4.4,2.75) 47(4.4,3.25) 48(4.4,3.75)
  oval 0.24x0.6 smd mask+0.07: 17(-3.751,-4.4) 18(-3.251,-4.4) 19(-2.751,-4.4) 20(-2.251,-4.4) 21(-1.75,-4.4) 22(-1.25,-4.4) 23(-0.75,-4.4) 24(-0.25,-4.4) 25(0.25,-4.4) 26(0.75,-4.4) 27(1.25,-4.4) 28(1.75,-4.4) 29(2.251,-4.4) 30(2.751,-4.4) 31(3.251,-4.4) 32(3.751,-4.4) 49(3.751,4.4) 50(3.251,4.4) 51(2.751,4.4) 52(2.251,4.4) 53(1.75,4.4) 54(1.25,4.4) 55(0.75,4.4) 56(0.25,4.4) 57(-0.25,4.4) 58(-0.75,4.4) 59(-1.25,4.4) 60(-1.75,4.4) 61(-2.251,4.4) 62(-2.751,4.4) 63(-3.251,4.4) 64(-3.751,4.4)
  rect 4.25x4.25 smd paste-2.112: 65(0,0)
  silkscreen extent -5.1,-5.1 5.1,5.1, body extent -4.57,-4.57 4.57,4.57, height 1.01
SOD-523F [mm] "COMCHIP"
  rect 0.6x0.8 smd paste-0.05: 1(-0.85,0) 2(0.85,0)
  silkscreen extent -1.92,-0.87 1.1,0.88, body extent -0.9,-0.5 0.9,0.5, height 0.85
TC2030-MCP-NL [mil] "TAG-CONNECT"
  round 31 smd paste-16: 1(-25,-50) 2(25,-50) 3(-25,0) 4(25,0) 5(-25,50) 6(25,50)
  round 25 hole 39 unplated: MH1(0,-100) MH2(-40,100) MH3(40,100)
  silkscreen extent -122,-195 118,195
TI_Symbol_Overlay_Small [mm]
  silkscreen extent -2.3,-2.23 2.3,2.24
TP_25MIL-SMT#1 [mm]
  round 0.635 smd mask-0.064: 1(0,0)
TP_25MIL-SMT#2 [mm]
  round 0.535 smd mask-0.064: 1(0,0)
TP_SM_1MM#1 [mm] "1mm Test Point, SMT"
  rrect50% 10x18 smd paste-0.5: 1(0,0)
TP_SM_1MM#2 [mm] "1mm Test Point, SMT"
  rrect50% 18x10 smd paste-0.5: 1(0,0)
TP_SM_1MM#3 [mm] "1mm Test Point, SMT"
  round 1 smd paste-0.5: 1(0,0)
Wurth_61201420621 [mm] "Header, 2.54mm, 7x2, SMT"
  rect 4x0.9 smd: 1(-3,7.62) 2(3,7.62) 3(-3,5.08) 4(3,5.08) 5(-3,2.54) 6(3,2.54) 7(-3,0) 8(3,0) 9(-3,-2.54) 10(3,-2.54) 11(-3,-5.08) 12(3,-5.08) 13(-3,-7.62) 14(3,-7.62)
  silkscreen extent -4.75,-12.7 4.4,12.7, body extent -4.75,-12.7 4.75,12.7, height 10.43

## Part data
1 2 3 4 5 6 7 8 9 10 11 12 13 14 15: "Test Point, O.025\""
BT3 BT4: "2x AA Battery Holder, Through-hole mount"
C1 C2 C12: "CAP, TA, 10 µF, 10 V, +/- 10%, 3.4 ohm, SMD"
C3 C6 C7 C10 C11 C13 C14 C18 C19 C23 C24 C28 C36 C37 C40 C42 C48 C50 C52: "CAP, CERM, 0.1 µF, 10 V, +/- 10%, X5R, 0402"
C4 C27: "CAP, CERM, 1 µF, 6.3 V, +/- 20%, X5R, 0402"
C5 C20: "CAP, CERM, 2.2 µF, 16 V, +/- 10%, X5R, 0402"
C8 C26 C38: "CAP, CERM, 0.01 µF, 25 V, +/- 10%, X7R, 0402"
C9 C15: "CAP, TA, 1 µF, 16 V, +/- 10%, 9.3 ohm, SMD"
C16 C17 C21 C22 C34 C35: "CAP, CERM, 10 µF, 6.3 V, +/- 20%, X5R, 0402"
C25 C46 C49 C53 C54: "CAP, CERM, 2200 pF, 50 V, +/- 10%, X8R, 0402"
C29: "CAP, CERM, 0.47 µF, 6.3 V, +/- 10%, X5R, 0402"
C30: "CAP, CERM, 33 pF, 50 V, +/- 5%, C0G/NP0, 0603"
C31: "CAP, CERM, 39pF, 50V, +/-5%, C0G/NP0, 0402"
C32: "CAP, CERM, 100 µF, 10 V, +/- 20%, X5R, 1206_190"
C33: library part Capacitor, "CAP, CERM, xxxF, xxV, [TempCo], xx%, [PackageReference]"
C39 C41 C55 C56: "CAP, CERM, 1 µF, 16 V, +/- 10%, X5R, 0402"
C43: "CAP, CERM, 1500 pF, 50 V, +/- 10%, X7R, 0603"
C44 C57: "CAP, CERM, 3000 pF, 50 V, +/- 5%, C0G/NP0, 0603"
C45 C47: "CAP, CERM, 4700 pF, 10 V, +/- 10%, X5R, 0402"
C51: "CAP, CERM, 10 µF, 6.3 V, +/- 20%, X5R, 0603"
C58 C59: "CAP, CERM, 10 pF, 50 V, +/- 5%, C0G/NP0, 0603"
D1 D2: "Diode, Schottky, 35V, 0.1A, SOD-523F"
FID1 FID2 FID3: "Fiducial mark.  There is nothing to buy or mount."
H1 H2 H3 H4: "Bumpon, Hemisphere, 0.375 X 0.235, Black"
H5 H6 H7 H8: "Machine Screw, Round, #4-40 x 1/4, Nylon, Philips panhead"
H9 H10 H11 H12: "Standoff, Hex, 0.5\"L #4-40 Nylon"
J1: "Footprint for TC2030-MCP-NL"
J2: "Header(Shrouded), 2.54mm, 7x2, Gold, Black, SMT"
J3: "CONN DB9 FEMALE R/A SOLDER TH"
L1 L2 L3 L4 L5 L6: "Ferrite Bead, 600 ohm @ 100MHz, 0.2A, 0603"
L7: "Inductor, Shielded, Ferrite, 4.7uH, 1.2A, 0.14 ohm, SMD"
Logo1: library part TI_Logo, "Texas Instrument Corporate Signature"
R1 R2 R3 R4 R5 R7 R13 R14 R16 R19: "RES, 0, 5%, 0.063 W, 0402"
R6: "RES, 47 k, 5%, 0.063 W, 0402"
R8: "RES, 21.5 k, 1%, 0.063 W, 0402"
R9: "RES, 10.0 k, 1%, 0.063 W, 0402"
R10 R15 R20: "RES, 1.00 M, 1%, 0.1 W, 0402"
R11: "RES, 11.8 k, 1%, 0.063 W, 0402"
R12: "RES, 8.06 k, 1%, 0.063 W, 0402"
R17: "RES, 200 k, 1%, 0.1 W, 0402"
R18: "RES, 4.99 k, 1%, 0.063 W, 0402"
R21 R22: "RES, 100 k, 1%, 0.1 W, 0402"
R23 R30: "RES, 51.1 k, 1%, 0.063 W, 0402"
R24 R25 R28 R29: "RES, 10.0 M, 1%, 0.063 W, 0402"
R26 R27: "RES, 40.2 k, 1%, 0.063 W, 0402"
R31 R32: "RES, 3.3 k, 5%, 0.063 W, 0402"
TP1 TP2 TP3 TP4 TP5: library part TP_SM_1MM, "1mm Test Point, SMT"
TP6: library part PogoPad, "Pad for Pogo Pin Connector"
U1: "Single Output High PSRR LDO, 200 mA, Fixed 3 V Output, 2.7 to 5.5 V Input, 5-pin SOT-23 (DBV), -40 to 85 degC, Green (RoHS & no Sb/Br)"
U2: "Single Micropower Precision Op Amp"
U3: "Precision Micropower Shunt Voltage Reference, 3-pin SOT-23"
U4: library part RF430CL331H, "The Texas Instruments Dynamic NFC Interface Transponder RF430CL331H is an NFC Tag Type 4 device  that combines a wireless NFC interface and a wired SPI or I2C interface to connect the device to a host."
U5: "LOW INPUT VOLTAGE STEP-UP CONVERTER IN 6 PIN SC-70 PACKAGE, DCK0006A"
U6: library part BMA250, "14 bit, digital, triaxial acceleration sensor with intelligent on-chip motion triggered interrupt controller"
U7: "High-Accuracy, Low-Power, Digital Temperature Sensor With SMBus(TM)/Two-Wire Serial Interface, DRL0006A"
U8: "Low-Power, 2-Channel, 24-Bit Analog Front-End for Biopotential Measurement, PBS0032A"
U9: "Mixed-Signal Microcontrollers, RGC0064B"
Y1: "Crystal, 32.768kHz, 12.5pF, SMD"
ZZ1: library part AssemblyNoteLabel
ZZ2 ZZ3 ZZ4: library part AssemblyNote

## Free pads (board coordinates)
  round 0 hole 3.762 unplated: 0(87.757,88.062)

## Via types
v1: diameter 0.864, hole 0.406, Top Layer to Bottom Layer, 104 vias
v2: diameter 0.5, hole 0.2, Top Layer to Bottom Layer, 13 vias

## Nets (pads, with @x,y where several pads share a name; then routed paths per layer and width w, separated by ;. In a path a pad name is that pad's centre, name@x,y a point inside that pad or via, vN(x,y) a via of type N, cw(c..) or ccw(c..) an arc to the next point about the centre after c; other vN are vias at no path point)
3V: C3.1 C4.1 C35.1 R4.2 R5.2 R15.2 U1.1 U1.3 U5.4 | length 53.6
  Top Layer w0.254: U1.3@92.996,102.55 U1.3@93.073,102.628 ; 94.234,100.178 94.336,100.178 ; C3.1@94.517,102.55 C3.1@94.594,102.628 ; 96.51,106.02 96.51,106.061
  Top Layer w0.54: R15.2@92.862,104.496 96.51,104.496 ; U1.1@92.996,100.65 93.762,100.65 94.234,100.178 ; U1.3@92.996,102.55 C3.1@94.517,102.55 ; 94.336,100.178 97.688,100.178 98.196,100.686 98.196,101.702 95.748,104.15 96.51,104.496 ; C3.1@94.594,102.628 C4.1@95.864,102.628 95.864,104.034 ; U5.4@95.494,109.662 95.494,110.632 95.86,110.998 97.333,110.998 97.841,110.49 ; C35.1@95.698,105.41 96.51,105.41 ; 96.51,106.02 96.51,105.41 ; 96.51,106.061 97.13,106.68 97.13,107.696 97.434,108.001 97.434,110.084 97.841,110.49 ; v1(100.482,113.132) 97.841,110.49 ; v1(103.022,115.672) 105.816,115.672 112.608,122.463 R5.2@112.608,124.816 ; R4.2@112.589,126.365 112.608,126.346 R5.2@112.608,124.861 ; 96.51,104.496 96.51,105.41
  Bottom Layer w0.54: v1(100.482,113.132) v1(103.022,115.672)
ADS1292_DRDY: 9.1 U8.22 U9.16 | length 19.6
  Top Layer w0.254: U8.22@89.294,138.704 89.294,137.039 89.56,136.773 v1(89.56,136.754) ; U9.16@94.468,128.312 v1(95.85,128.312) 96.164,127.998 9.1@96.164,127.356
  Bottom Layer w0.254: v1(89.56,136.754) 89.56,134.602 93.504,130.658 ; 93.504,130.658 v1(95.85,128.312) 95.85,129.448 94.64,130.658 93.504,130.658
ADS1292_ELA: C52.1 J3.2 R30.1 TP4.1 | length 93.4
  Top Layer w1: R30.1@83.613,151.409 83.613,154.733 ; J3.2@87.375,160.454 87.376,157.302 ; C52.1@93.37,152.086 93.37,153.518 92.1,154.788 83.613,154.733 ; TP4.1@145.11,143.358 145.11,153.822 141.63,157.302 88.544,157.302 84.887,157.302 83.613,156.028 83.613,154.733
ADS1292_ERA: C48.1 J3.1 R23.1 TP3.1 | length 92.4
  Top Layer w0.54: R23.1@84.887,151.437 v1@84.887,153.67
  Top Layer w1: TP3.1@28.677,143.358 28.677,153.822 31.267,156.413 78.918,156.413 82.958,160.454 J3.1@84.605,160.454 ; v1(94.59,155.143) 94.64,155.092 C48.1@94.64,152.086
  Bottom Layer w0.54: v1@84.887,153.67 85.7,154.534
  Bottom Layer w1: J3.1@84.605,160.454 84.605,156.873 84.887,156.591 84.887,153.67 v1(84.887,153.314) ; 85.09,155.143 v1(94.59,155.143)
ADS1292_GPIO1: 6.1 U8.26 U9.14 | length 24.5
  Top Layer w0.254: U8.26@91.694,140.603 93.077,140.603 94.591,139.089 94.591,137.976 96.575,135.992 ; U9.14@94.468,127.312 95.192,127.312 96.914,125.59 v1@96.914,125.336 ; 6.1@95.148,131.674 96.019,131.674 v1(96.425,132.08) 96.581,132.236 96.581,135.992
  Bottom Layer w0.254: v1(96.425,132.08) 98.45,130.055 98.45,126.848 v1(96.926,125.324)
ADS1292_GPIO2: 7.1 U8.25 U9.25 | length 20.5
  Top Layer w0.254: U9.25@89.818,128.962 89.818,129.729 ; 89.818,129.73 89.818,131.626 91.034,132.842 95.606,132.842 96.164,133.401 96.164,135.839 94.137,137.866 94.137,138.8 92.834,140.103 U8.25@91.694,140.103 ; 89.818,131.166 7.1@91.338,131.166
ADS1292_IN1N: C46.1 R24.1 R25.2 U8.3 | length 12.8
  Top Layer w0.254: R24.1@89.144,152.202 89.814,152.202 ; U8.3@89.294,145.003 89.294,148.184 89.56,148.45 v1(89.56,148.946) ; 89.37,147.753 90.053,147.753 C46.1@90.738,148.438 ; v1(89.814,153.264) 89.814,152.202 ; R25.2@90.738,152.202 89.814,152.202
  Bottom Layer w0.254: v1(89.56,148.946) 89.56,150.932 89.814,151.186 v1(89.814,153.264)
ADS1292_IN1P: C54.1 R28.1 R29.2 U8.4 | length 9.1
  Top Layer w0.254: U8.4@88.794,145.003 88.794,149.246 89.256,149.708 C54.1@90.738,149.708 ; R28.1@89.144,150.932 89.941,150.932 ; 89.941,149.835 89.941,150.932 ; R29.2@90.738,150.932 89.941,150.932
ADS1292_IN2N: C44.1 R23.2 U8.5 | length 8.7
  Top Layer w0.254: C44.1@86.411,150.291 84.941,150.291 R23.2@84.887,150.237 84.887,149.447 85.242,149.092 86.127,149.092 86.411,148.807 88.294,146.924 U8.5@88.294,145.003
ADS1292_IN2P: C57.1 R30.2 U8.6 | length 9.5
  Top Layer w0.254: C57.1@82.089,150.263 83.559,150.263 R30.2@83.613,150.209 ; R30.2@83.559,150.209 83.559,149.359 84.28,148.638 85.938,148.638 87.794,146.782 U8.6@87.794,145.003
ADS1292_MAIN_CLKSEL: 14.1 U8.14 U9.32 | length 17.1
  Top Layer w0.254: U8.14@85.395,141.103 83.984,141.103 83.318,140.437 83.318,130.658 83.826,130.15 86.004,130.15 ; 14.1@86.004,130.912 86.004,130.15 ; U9.32@86.317,128.962 86.317,129.837 86.004,130.15
ADS1292_RESET: 8.1 U8.15 U9.31 | length 16.9
  Top Layer w0.254: 8.1@85.242,132.944 85.242,131.597 ; U8.15@85.395,140.603 85.375,140.583 84.28,140.583 83.772,140.075 83.772,132.128 84.303,131.597 85.242,131.597 ; U9.31@86.818,128.962 86.818,131.368 86.589,131.597 85.242,131.597
ADS1292_RESP_MODP/IN3N: R26.2 U8.32 | length 2.4
  Top Layer w0.254: U8.32@91.694,143.603 93.362,143.603 93.37,143.612 R26.2@93.37,144.328
ADS1292_RESP_MODP/IN3P: R27.2 TP6.1 U8.31 | length 13.4
  Top Layer w0.254: U8.31@91.694,143.103 93.416,143.103 R27.2@94.64,144.328 97.642,144.328 98.45,145.136 TP6.1@98.45,150.901
ADS1292_RLD: J3.4 R22.2 TP5.1 | length 3.2
  Top Layer w0.254: R22.2@103.114,147.168 104.8,147.168 v1(105.308,146.66)
  Bottom Layer w0.254: v1(105.308,146.66) 105.842,146.126
ADS1292_SPI_CS: 10.1 U8.18 U9.29 | length 14.1
  Top Layer w0.254: 85.334,135.23 10.1@86.512,135.23 ; 87.248,137.328 86.462,136.541 85.842,136.541 85.242,135.941 85.242,134.722 85.496,134.468 87.121,134.468 87.818,133.771 U9.29@87.818,128.962 ; 87.294,137.374 U8.18@87.294,138.704
ADS1292_SPI_DIN: 12.1 U8.19 U9.26 | length 17.3
  Top Layer w0.254: 12.1@81.94,135.23 81.94,135.992 82.194,136.246 v1(82.194,136.5) ; v1@87.794,136.766 U8.19@87.794,138.704 ; U9.26@89.318,128.962 89.318,132.143 v1(89.764,132.588)
  Bottom Layer w0.254: v1(82.194,136.5) v1(87.528,136.5) 87.528,134.823 v1(89.764,132.588)
ADS1292_SPI_DOUT: 11.1 U8.21 U9.27 | length 29.7
  Top Layer w0.254: U9.27@88.818,128.962 88.818,134.074 88.794,134.098 U8.21@88.794,138.704 88.794,140.052 v1(89.56,140.818) ; v1(99.974,147.93) 99.974,149.2 11.1@102.006,151.232
  Bottom Layer w0.254: v1(89.56,140.818) 93.624,144.882 96.926,144.882 v1(99.974,147.93)
ADS1292_SPI_SCLK: 13.1 U8.20 U9.28 | length 21.9
  Top Layer w0.254: 13.1@81.89,147.32 82.652,146.558 84.176,146.558 v1(84.684,146.05) ; v1(87.782,140.31) 88.29,139.802 88.29,133.96 88.318,133.932 U9.28@88.318,128.962
  Bottom Layer w0.254: v1(84.684,146.05) 84.684,143.408 v1(87.782,140.31)
ADS1292_START: 15.1 U8.16 U9.30 | length 15.2
  Top Layer w0.254: 84.226,137.77 15.1@84.988,137.77 ; U8.16@85.395,140.103 84.508,140.103 84.226,139.821 84.226,138.204 84.226,134.722 84.988,133.96 86.766,133.96 87.318,133.408 U9.30@87.318,128.962
ADS1292_VCAP1: C55.1 U8.11 | length 4.6
  Top Layer w0.254: C55.1@80.816,142.603 U8.11@85.395,142.603
ADS1292_VCAP2: C56.1 U8.27 | length 6.8
  Top Layer w0.254: U8.27@91.694,141.103 93.492,141.103 95.045,139.55 95.045,138.022 95.552,137.516 C56.1@96.072,137.516
ADS1292_VREFP: C50.1 C51.1 U8.9 | length 5.9
  Top Layer w0.254: C51.1@81.677,145.58 C51.1@81.382,145.58 81.49,145.472 C50.1@82.906,145.472 83.738,145.472 83.922,145.288 83.922,144.018 84.336,143.603 U8.9@85.395,143.603
ADS_AVCC: C22.1 C23.1 C24.1 C39.1 C40.1 L6.2 R8.2 R24.2 R28.2 U2.5 U8.12 | length 21.4
  Top Layer w0.254: U2.5@76.144,143.8 77.099,143.8 77.318,144.018 v1(77.318,144.78) ; v1(76.556,145.542) 76.604,145.493 77.777,145.493 78.384,146.101 R8.2@78.384,147.33 ; v1(78.334,136.906) 78.697,137.27 79.55,137.27 C23.1@79.608,137.212 ; v1(78.926,141.106) C39.1@80.878,141.106 ; L6.2@79.654,135.522 79.654,137.166 C23.1@79.608,137.212 ; v1(80.67,148.184) C24.1@80.67,150.378 ; C22.1@80.878,137.212 C23.1@79.608,137.212 ; C39.1@81.178,141.164 C40.1@82.448,141.164 83.388,142.103 U8.12@85.395,142.103 ; v1(87.944,149.362) R28.2@87.944,150.932 R24.2@87.944,152.202
ADS_AVSS: C22.2 C23.2 C24.2 C39.2 C40.2 C44.2 C50.2 C51.2 C55.2 C56.2 C57.2 J3.10 J3.11 R3.2 R9.1 R12.1 R25.1 R29.1 U2.2 U3.2 U8.10 U8.13 | length 43.8
  Top Layer w0.254: v1(68.053,123.489) R3.2@69.869,123.489 ; v1(72.658,142.85) U2.2@73.744,142.85 ; R12.1@75.799,148.117 74.828,149.088 74.828,151.74 75.524,152.436 78.776,152.436 80.604,152.436 ; v1@77.876,143.612 v1(78.13,143.612) 78.13,143.205 78.74,142.596 C55.2@79.608,142.596 ; v1(79.858,146.304) 79.858,144.272 80.15,143.98 C51.2@81.382,143.98 81.674,144.272 C50.2@82.906,144.272 82.906,143.51 83.312,143.104 83.921,143.104 U8.10@85.395,143.103 ; C24.2@80.67,151.578 v1(80.67,153.518) ; C22.2@80.878,138.412 79.608,138.412 79.608,139.906 80.878,139.906 82.044,139.906 C40.2@82.275,140.137 ; C57.2@82.089,151.863 v1(82.089,153.496) ; C40.2@82.448,139.964 82.448,140.068 83.742,141.362 ; 83.742,141.373 83.972,141.603 U8.13@85.395,141.603 ; C44.2@86.411,151.891 v1(86.411,153.416) ; R29.1@91.938,150.932 R25.1@91.938,152.202 v1(91.938,153.426) ; C56.2@97.272,137.516 97.272,136.916 v1(97.688,136.5)
  Top Layer w0.54: v1(104.038,135.484) R9.1@104.038,137.17
  other v1: 79.908,139.906
ADS_DVCC: C15.1 C19.1 C20.1 C21.1 C41.1 C42.1 L5.2 L6.1 U8.23 | length 24.7
  Top Layer w0.254: L6.1@79.654,133.972 79.908,133.972 v1(79.908,132.436) ; 89.56,135.484 89.56,134.376 89.814,134.122 C42.1@90.576,134.122 C41.1@91.846,134.122 C19.1@93.116,134.122 C20.1@94.386,134.122 ; 89.577,135.5 90.322,136.246 90.322,137.008 89.794,137.536 U8.23@89.794,138.704 ; C20.1@94.415,134.15 C20.1@94.386,134.122 ; v1(95.352,133.858) 95.352,133.896 95.126,134.122 C20.1@94.386,134.122 ; v1(97.688,132.944) C21.1@97.688,134.122 98.358,133.452 L5.2@99.682,133.452 99.682,134.176 100.736,135.23 100.736,139.294 99.974,140.056 C15.1@99.974,141.296
ANTENNA: D1.2 D2.2 R13.2 R14.2 | length 600.2
  Top Layer w0.4: v1(77.114,95.86) 77.876,96.622 98.704,96.622 98.704,73 76.352,73 76.352,97.13 99.212,97.13 99.212,72.492 75.844,72.492 75.844,97.638 99.72,97.638 99.72,71.984 75.286,71.984 75.286,98.044 76.098,98.857 76.098,103.631 76.654,104.055 77.745,104.055 ; v1(77.114,100.178) 77.114,101.702 77.724,102.311 84.48,102.311 84.811,102.641 D2.2@84.811,103.239 ; D1.2@77.745,106.379 77.745,104.055 ; R13.2@79.523,104.055 77.745,104.055 ; 81.047,102.311 R14.2@81.047,104.055
  Bottom Layer w0.4: 75.286,97.079 75.286,71.984 99.72,71.984 99.72,97.638 77.114,97.638 v1(77.114,100.178) ; 75.336,97.13 99.212,97.13 99.212,72.492 75.844,72.492 75.844,96.622 98.704,96.622 98.704,73 76.352,73 76.352,95.098 v1(77.114,95.86)
BMA_AVCC: C16.1 C37.1 L4.1 U6.7 | length 5.4
  Top Layer w0.254: C16.1@74.066,128.647 C37.1@75.336,128.647 ; U6.7@75.069,127.111 75.069,128.38 C37.1@75.336,128.647 ; L4.1@76.822,129.896 76.822,129.045 76.583,128.805 75.495,128.805 C37.1@75.336,128.647
BMA_DVCC: C17.1 C36.1 L3.2 L4.2 U6.1 U6.3 U6.11 | length 28.6
  Top Layer w0.254: U6.11@75.594,125.586 75.594,124.794 75.311,124.511 73.965,124.511 72.695,125.781 72.695,129.616 74.193,131.115 78.054,131.115 78.422,130.747 L4.2@78.422,129.896 78.422,129.096 79.4,128.118 L3.2@80.378,128.118 80.416,128.08 C17.1@80.416,126.224 C36.1@79.146,126.224 78.759,126.611 U6.3@76.619,126.611 ; U6.1@76.619,125.611 76.619,125.158 77.064,124.714 77.927,124.714 78.41,125.197 78.41,126.585
BMA_INT1: U6.5 U9.38 | length 11
  Top Layer w0.254: U6.5@76.094,127.136 76.094,127.657 76.23,127.792 v1(76.705,127.792) ; v1(82.194,126.848) 83.21,125.832 ; 83.23,125.812 U9.38@85.668,125.812
  Bottom Layer w0.254: v1(76.705,127.792) 77.674,127.792 78.692,126.774 79.238,126.774 79.311,126.848 v1(82.194,126.848)
BMA_INT2: U6.6 U9.33 | length 12.2
  Top Layer w0.254: U6.6@75.594,127.136 75.594,127.88 76.166,128.451 77.241,128.451 77.568,128.778 v1(77.648,128.778) ; v1(83.922,129.286) 83.922,128.676 84.286,128.312 U9.33@85.668,128.312
  Bottom Layer w0.254: v1(77.648,128.778) 83.414,128.778 v1(83.922,129.286)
